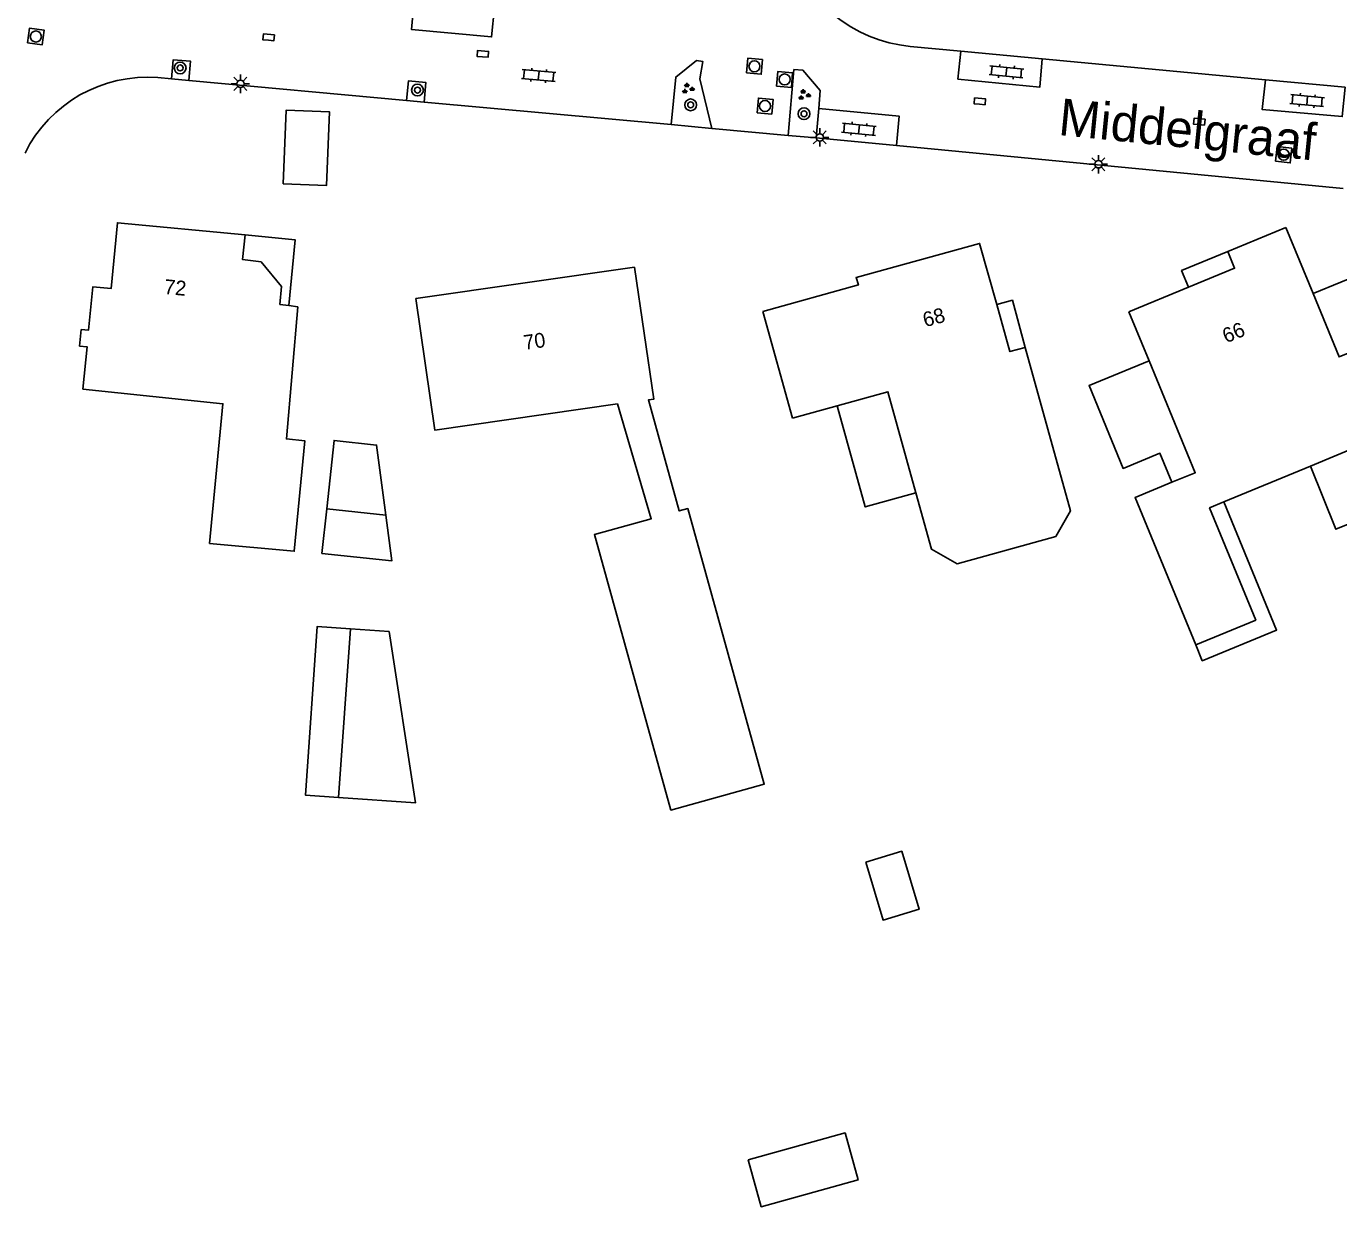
# Model space of a CAD drawing. Extents: x 131000 to 133013, y 393000 to 396501.
# Drawn here: x 131087.6 to 131176.6, y 394744.1 to 394824.1 of the extents above; entities that cross this region are included whole.
import ezdxf

# ---------------------------------------------------------------- set-up
doc = ezdxf.new("R2010")
doc.units = 0
for name, color, linetype in [('gg-anno-huisnummerreeks BGT', 7, 'Continuous'), ('gg-anno-openbare ruimte label', 7, 'Continuous'), ('gg-bbg-gedigitaliseerde bebouwing', 7, 'Continuous'), ('gg-bbg-gedigitaliseerde bijgebouw', 7, 'Continuous'), ('gg-bbg-hoofdgebouw', 7, 'Continuous'), ('gg-bbg-luifel en loopbrug', 7, 'Continuous'), ('gg-knt-verharding', 7, 'Continuous'), ('gg-knt-verharding nz', 7, 'Continuous'), ('gt-grn-vlakafsluiter', 7, 'Continuous'), ('gt-symb-boom', 7, 'Continuous'), ('gt-symb-groenvak', 7, 'Continuous'), ('gt-symb-klinker verharding', 7, 'Continuous'), ('gt-symb-kolk', 7, 'Continuous'), ('gt-symb-lichtmast', 7, 'Continuous'), ('gt-symb-rioolschacht', 7, 'Continuous')]:
    doc.layers.add(name, color=color, linetype=linetype)

# ---------------------------------------------------------------- blocks, each defined once
blk = doc.blocks.new('gt0-BOOM')
at = {"layer": 'gt-symb-boom'}
for radius in [0.4, 0.2]:
    blk.add_circle((0, 0), radius, dxfattribs=at)
blk = doc.blocks.new('gt0-RS')
at = {"layer": 'gt-symb-rioolschacht'}
blk.add_lwpolyline([(-0.5, -0.5), (0.5, -0.5), (0.5, 0.5), (-0.5, 0.5)], close=True, dxfattribs=at)
blk.add_circle((0, 0), 0.375, dxfattribs=at)
blk = doc.blocks.new('gt0-LMAST')
at = {"layer": 'gt-symb-lichtmast'}
for p, q in [((-0.182, 0.173), (-0.447, 0.438)), ((-0.005, 0.246), (-0.005, 0.621)), ((0.172, 0.173), (0.437, 0.438)), ((-0.255, -0.004), (-0.63, -0.004)), ((-0.182, -0.181), (-0.447, -0.446)), ((-0.005, -0.254), (-0.005, -0.629)), ((0.437, -0.446), (0.172, -0.181)), ((0.245, -0.004), (0.62, -0.004))]:
    blk.add_line(p, q, dxfattribs=at)
blk.add_circle((-0.005, -0.004), 0.25, dxfattribs=at)
blk = doc.blocks.new('gt0-KOLK')
at = {"layer": 'gt-symb-kolk'}
blk.add_lwpolyline([(0, 0), (0.375, 0), (0.375, 0.4), (-0.375, 0.4), (-0.375, 0), (0, 0)], dxfattribs=at)
blk = doc.blocks.new('gt0-KL1')
at = {"layer": 'gt-symb-klinker verharding'}
for p, q in [((-1.15, 0.3), (1.15, 0.3)), ((-1, -0.3), (-1, 0.3)), ((-0.5, 0.3), (-0.5, 0.45)), ((0, -0.3), (0, 0.3)), ((0.5, 0.3), (0.5, 0.45)), ((1, -0.3), (1, 0.3)), ((-1.15, -0.3), (1.15, -0.3)), ((-0.5, -0.45), (-0.5, -0.3)), ((0.5, -0.45), (0.5, -0.3))]:
    blk.add_line(p, q, dxfattribs=at)
blk = doc.blocks.new('gt0-GRVAK')
at = {"layer": 'gt-symb-groenvak'}
for p, q in [((-0.11, 0.189), (-0.228, 0.24)), ((-0.182, 0.153), (0.088, 0.153)), ((-0.091, 0.211), (-0.156, 0.322)), ((-0.047, 0.214), (-0.047, 0.393)), ((-0.004, 0.211), (0.061, 0.322)), ((0.015, 0.189), (0.133, 0.24)), ((0.262, -0.052), (0.197, 0.059)), ((0.305, -0.049), (0.305, 0.13)), ((0.349, -0.052), (0.414, 0.059)), ((-0.245, -0.228), (-0.363, -0.177)), ((-0.318, -0.264), (-0.047, -0.264)), ((-0.226, -0.206), (-0.291, -0.095)), ((-0.183, -0.203), (-0.183, -0.024)), ((-0.139, -0.206), (-0.074, -0.095)), ((-0.12, -0.228), (-0.002, -0.177)), ((0.243, -0.074), (0.125, -0.023)), ((0.17, -0.11), (0.441, -0.11)), ((0.368, -0.074), (0.486, -0.023))]:
    blk.add_line(p, q, dxfattribs=at)

msp = doc.modelspace()

# ---------------------------------------------------------------- linework, layer by layer
at = {"layer": 'gg-bbg-gedigitaliseerde bebouwing'}
for p, q in [((131137.556, 394804.778), (131139.56, 394797.56)), ((131163.732, 394801.435), (131162.353, 394804.768)), ((131142.599, 394798.399), (131139.56, 394797.56)), ((131174.667, 394794.312), (131177.984, 394795.686)), ((131174.667, 394794.312), (131168.802, 394791.882))]:
    msp.add_line(p, q, dxfattribs=at)
for points in [[(131128.864, 394807.789), (131130.17, 394798.85), (131129.8, 394798.81), (131131.89, 394791.27), (131132.47, 394791.43), (131137.65, 394772.76), (131131.32, 394771), (131126.14, 394789.67), (131129.99, 394790.74), (131127.7, 394798.52), (131115.33, 394796.74), (131114.029, 394805.676)], [(131106.045, 394805.112), (131105.26, 394796.15), (131106.51, 394796.03), (131105.79, 394788.54), (131100.05, 394789.07), (131100.96, 394798.54), (131091.468, 394799.514)], [(131155.343, 394802.359), (131158.402, 394791.279), (131157.412, 394789.533), (131150.727, 394787.688), (131148.981, 394788.678), (131147.929, 394792.491)], [(131165.284, 394793.214), (131166.863, 394793.864), (131163.732, 394801.435)], [(131147.929, 394792.491), (131146.037, 394799.348), (131142.599, 394798.399)], [(131165.284, 394793.214), (131162.781, 394792.182), (131166.896, 394782.196)], [(131166.896, 394782.196), (131170.964, 394783.873), (131167.83, 394791.479), (131168.802, 394791.882)]]:
    msp.add_lwpolyline(points, dxfattribs=at)
at = {"layer": 'gg-bbg-gedigitaliseerde bijgebouw'}
for p, q in [((131111.996, 394790.976), (131107.994, 394791.408)), ((131109.599, 394783.288), (131108.792, 394771.858)), ((131112.231, 394783.102), (131109.599, 394783.288))]:
    msp.add_line(p, q, dxfattribs=at)
for points in [[(131107.994, 394791.408), (131107.668, 394788.393), (131112.403, 394787.882), (131111.996, 394790.976)], [(131108.792, 394771.858), (131114.014, 394771.49), (131112.231, 394783.102)], [(131144.53, 394767.475), (131145.702, 394763.543), (131148.141, 394764.27), (131146.969, 394768.202), (131144.53, 394767.475)]]:
    msp.add_lwpolyline(points, dxfattribs=at)
at = {"layer": 'gg-bbg-hoofdgebouw'}
for p, q in [((131173.012, 394810.478), (131169.064, 394808.852)), ((131173.012, 394810.478), (131174.85, 394806.003)), ((131128.864, 394807.789), (131114.029, 394805.676)), ((131166.407, 394806.439), (131162.353, 394804.768)), ((131106.045, 394805.112), (131105.421, 394805.191))]:
    msp.add_line(p, q, dxfattribs=at)
for points in [[(131102.463, 394809.98), (131093.813, 394810.809), (131093.38, 394806.341), (131092.141, 394806.458), (131091.842, 394803.514), (131091.354, 394803.568), (131091.242, 394802.441), (131091.759, 394802.385), (131091.468, 394799.514)], [(131105.421, 394805.191), (131104.824, 394805.266), (131104.932, 394806.488), (131103.548, 394808.164), (131102.287, 394808.305), (131102.463, 394809.98)], [(131153.404, 394805.26), (131152.244, 394809.403), (131143.873, 394807.092), (131144.039, 394806.594), (131137.556, 394804.778)], [(131169.064, 394808.852), (131169.528, 394807.725), (131166.407, 394806.439)], [(131174.85, 394806.003), (131176.613, 394801.713), (131178.01, 394802.273), (131179.422, 394798.834)], [(131155.343, 394802.359), (131154.297, 394802.073), (131153.404, 394805.26)]]:
    msp.add_lwpolyline(points, dxfattribs=at)
at = {"layer": 'gg-bbg-luifel en loopbrug'}
for points in [[(131105.041, 394813.445), (131107.976, 394813.322), (131108.186, 394818.32), (131105.25, 394818.443), (131105.041, 394813.445)], [(131102.463, 394809.98), (131105.849, 394809.655), (131105.421, 394805.191)], [(131169.064, 394808.852), (131165.942, 394807.566), (131166.407, 394806.439)], [(131174.85, 394806.003), (131178.606, 394807.546), (131180.634, 394802.61), (131179.429, 394802.115), (131180.579, 394799.316)], [(131155.343, 394802.359), (131154.47, 394805.551), (131153.404, 394805.26)], [(131163.732, 394801.435), (131159.666, 394799.765), (131161.969, 394794.157), (131164.474, 394795.186), (131165.284, 394793.214)], [(131147.929, 394792.491), (131144.492, 394791.542), (131142.599, 394798.399)], [(131111.996, 394790.976), (131111.371, 394795.735), (131108.495, 394796.046), (131107.994, 394791.408)], [(131179.72, 394791.37), (131176.383, 394790.033), (131174.667, 394794.312)], [(131168.802, 394791.882), (131172.378, 394783.198), (131167.338, 394781.122), (131166.896, 394782.196)], [(131109.599, 394783.288), (131107.354, 394783.447), (131106.546, 394772.017), (131108.792, 394771.858)], [(131136.563, 394747.298), (131137.444, 394744.109), (131144.015, 394745.924), (131143.134, 394749.114), (131136.563, 394747.298)]]:
    msp.add_lwpolyline(points, dxfattribs=at)
at = {"layer": 'gg-knt-verharding'}
for p, q in [((131147.542, 394822.759), (131150.985, 394822.436)), ((131150.985, 394822.436), (131156.499, 394821.919)), ((131171.628, 394820.501), (131156.499, 394821.919)), ((131096.558, 394820.64), (131097.478, 394820.556)), ((131097.478, 394820.556), (131098.65, 394820.448)), ((131098.65, 394820.448), (131113.411, 394819.096)), ((131171.628, 394820.501), (131177.026, 394819.996)), ((131113.411, 394819.096), (131114.594, 394818.988)), ((131114.594, 394818.988), (131131.336, 394817.454)), ((131141.175, 394816.552), (131141.345, 394818.54)), ((131134.106, 394817.2), (131139.28, 394816.726)), ((131146.614, 394816.03), (131141.175, 394816.552)), ((131176.892, 394813.123), (131146.614, 394816.03))]:
    msp.add_line(p, q, dxfattribs=at)
for points in [[(131097.478, 394820.556), (131097.597, 394821.854), (131098.77, 394821.754), (131098.65, 394820.448)], [(131131.336, 394817.454), (131131.657, 394820.68), (131133.066, 394821.807), (131133.484, 394821.742), (131133.287, 394820.554), (131134.106, 394817.2)], [(131141.345, 394818.54), (131141.449, 394819.759), (131140.273, 394821.139), (131139.659, 394821.182), (131139.28, 394816.726)], [(131113.411, 394819.096), (131113.532, 394820.416), (131114.715, 394820.31), (131114.594, 394818.988)]]:
    msp.add_lwpolyline(points, dxfattribs=at)
for centre, radius, start, end in [((131148.434, 394832.276), 9.559, 196.66411, 264.64316), ((131095.838, 394811.405), 9.263, 85.54123, 153.54243)]:
    msp.add_arc(centre, radius, start, end, dxfattribs=at)
at = {"layer": 'gg-knt-verharding nz'}
for points in [[(131119.372, 394825.401), (131119.172, 394823.397), (131113.736, 394823.911), (131113.918, 394825.896)], [(131150.985, 394822.436), (131150.783, 394820.542), (131156.335, 394820.004), (131156.499, 394821.919)], [(131171.628, 394820.501), (131171.394, 394818.486), (131176.832, 394817.997), (131177.026, 394819.996)], [(131141.345, 394818.54), (131146.796, 394818.026), (131146.614, 394816.03)]]:
    msp.add_lwpolyline(points, dxfattribs=at)
at = {"layer": 'gt-grn-vlakafsluiter'}
for p, q in [((131134.106, 394817.2), (131131.336, 394817.454)), ((131141.175, 394816.552), (131139.28, 394816.726))]:
    msp.add_line(p, q, dxfattribs=at)

# ---------------------------------------------------------------- block references
at = {"layer": 'gt-symb-boom'}
for p in [(131098.059, 394821.299), (131114.147, 394819.797), (131132.663, 394818.794), (131140.345, 394818.192)]:
    msp.add_blockref('gt0-BOOM', p, dxfattribs=at)
at = {"layer": 'gt-symb-groenvak'}
for p in [(131132.461, 394819.896), (131140.337, 394819.463)]:
    msp.add_blockref('gt0-GRVAK', p, dxfattribs=at)
at = {"layer": 'gt-symb-klinker verharding'}
for p, rotation in [((131154.065, 394821.032), -5.568024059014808), ((131122.362, 394820.786), -5.220361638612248), ((131174.449, 394819.084), -5.5680240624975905), ((131144.067, 394817.137), -5.625060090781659)]:
    msp.add_blockref('gt0-KL1', p, dxfattribs=dict(at, rotation=rotation))
at = {"layer": 'gt-symb-kolk'}
for p, rotation in [((131104.045, 394823.17), -4.9349859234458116), ((131118.563, 394822.051), -4.934985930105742), ((131152.245, 394818.836), -5.510976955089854), ((131167.117, 394817.455), -5.51097695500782)]:
    msp.add_blockref('gt0-KOLK', p, dxfattribs=dict(at, rotation=rotation))
at = {"layer": 'gt-symb-lichtmast'}
for p in [(131102.152, 394820.224), (131141.419, 394816.591), (131160.307, 394814.772)]:
    msp.add_blockref('gt0-LMAST', p, dxfattribs=at)
at = {"layer": 'gt-symb-rioolschacht'}
for p, rotation in [((131088.28, 394823.427), -8.340866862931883), ((131136.987, 394821.41), -4.934985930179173), ((131139.033, 394820.517), -4.934985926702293), ((131137.706, 394818.713), -4.9349859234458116), ((131172.862, 394815.417), 173.10945167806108)]:
    msp.add_blockref('gt0-RS', p, dxfattribs=dict(at, rotation=rotation))

# ---------------------------------------------------------------- texts
at = {"layer": 'gg-anno-huisnummerreeks BGT'}
for s, rotation, p in [('72', 354.5, (131096.944, 394805.988)), ('68', 15.4, (131148.559, 394803.718)), ('66', 22.4, (131168.958, 394802.623)), ('70', 8.1, (131121.402, 394802.181))]:
    msp.add_text(s, height=1, rotation=rotation, dxfattribs=at).set_placement(p)
at = {"layer": 'gg-anno-openbare ruimte label'}
msp.add_text('Middelgraaf', height=2.5, rotation=354.3, dxfattribs=at).set_placement((131157.533, 394816.757))

doc.saveas('drawing.dxf')
